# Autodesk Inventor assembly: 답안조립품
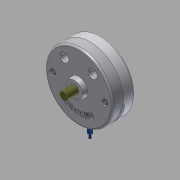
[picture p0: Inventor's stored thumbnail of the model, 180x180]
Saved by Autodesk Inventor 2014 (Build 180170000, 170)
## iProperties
Created: 2015-06
Part Number: 답안조립품
Document SubType Name: Assembly
Designer: MYHOME
Author: MYHOME
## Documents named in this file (10)
- C:\Documents and Settings\MYHOME\바탕 화면\450631V1041\답안조립품.iam
- C:\Documents and Settings\MYHOME\바탕 화면\450631V1041\본체.ipt
- C:\Documents and Settings\MYHOME\바탕 화면\450631V1041\덮개.ipt
- C:\Documents and Settings\MYHOME\바탕 화면\450631V1041\베어링62_22.ipt
- C:\Documents and Settings\MYHOME\바탕 화면\450631V1041\M10x35.ipt
- C:\Documents and Settings\MYHOME\바탕 화면\450631V1041\축.ipt
- C:\Documents and Settings\MYHOME\바탕 화면\450631V1041\멈춤링.ipt
- C:\Documents and Settings\MYHOME\바탕 화면\450631V1041\슬라이더2.ipt
- C:\Documents and Settings\MYHOME\바탕 화면\450631V1041\슬라이더.ipt
- C:\Documents and Settings\MYHOME\바탕 화면\450631V1041\평행핀.ipt
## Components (9 placed, 4 different names)
1. KS B 2023 62/22 - 22 x 50 x 14:1
2. KS B 2023 62/22 - 22 x 50 x 14:2
3. KS B 1336 22 x 1.2:1
4. KS B 1336 22 x 1.2:2
5. KS B 1320 B B 5 x  20:1
6. KS B 1003 - 미터 M 10 x 35:1
7. KS B 1003 - 미터 M 10 x 35:2
8. KS B 1003 - 미터 M 10 x 35:3
9. KS B 1003 - 미터 M 10 x 35:4
